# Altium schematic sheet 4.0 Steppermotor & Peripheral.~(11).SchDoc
size A4; SheetNumber: 4; SheetTotal: 7
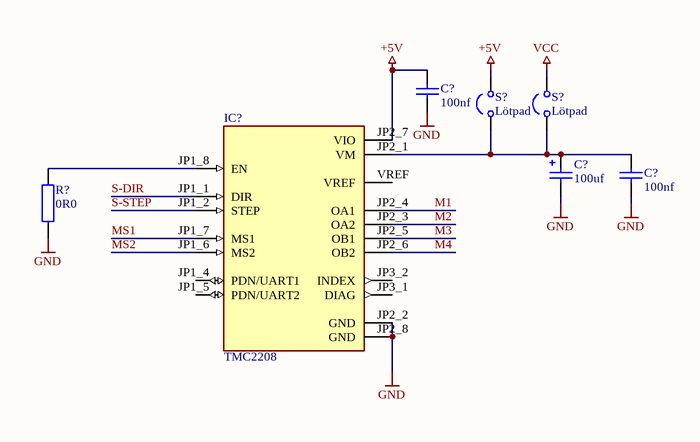
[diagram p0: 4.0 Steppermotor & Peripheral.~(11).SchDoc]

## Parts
(Parts that share a designator on the sheet are numbered #1, #2 ... from top to bottom, then left to right.)
C?#1  100nf  [C_SMD_0805]
C?#2  100uf  [C_SMD_D-TYP]
C?#3  100nf  [C_SMD_0805]
IC?  TMC2208  [IC_TMC2208]
R?  0R0  [R_SMD_0805]
S?#1  Lötpad  [S_SMD_Pad-NC]
S?#2  Lötpad  [S_SMD_Pad-NO]

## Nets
+5V: C?#1.1 IC?.JP2_7(VIO) S?#1.2
GND: C?#1.2 C?#2.2 C?#3.2 IC?.JP2_2(GND) IC?.JP2_8(GND) R?.1
VCC: S?#2.2
M1: IC?.JP2_4(OA1)
M2: IC?.JP2_3(OA2)
M3: IC?.JP2_5(OB1)
M4: IC?.JP2_6(OB2)
MS1: IC?.JP1_7(MS1)
MS2: IC?.JP1_6(MS2)
S-DIR: IC?.JP1_1(DIR)
S-STEP: IC?.JP1_2(STEP)
NetC?#2_1: C?#2.1 C?#3.1 IC?.JP2_1(VM) S?#1.1 S?#2.1
NetIC?_JP1_8: IC?.JP1_8(EN) R?.2

Not connected (* = marked no-connect by the designer): IC? JP1_4(PDN/UART1) JP1_5(PDN/UART2) JP3_1(DIAG) JP3_2(INDEX) VREF

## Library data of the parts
C?#1 C?#3 = C_SMD_KO: Kondensator SMD Universal, Keramik, Folie, usw.
C?#2 = C_SMD_ELK: SMD Elektrolytkondensator
IC? = IC_TMC2208: Schrittmotortreiber
R? = R_SMD_Widerstand: Widerstand SMD
S?#1 S?#2 = S_SMD_Jumper: Lötverbinder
